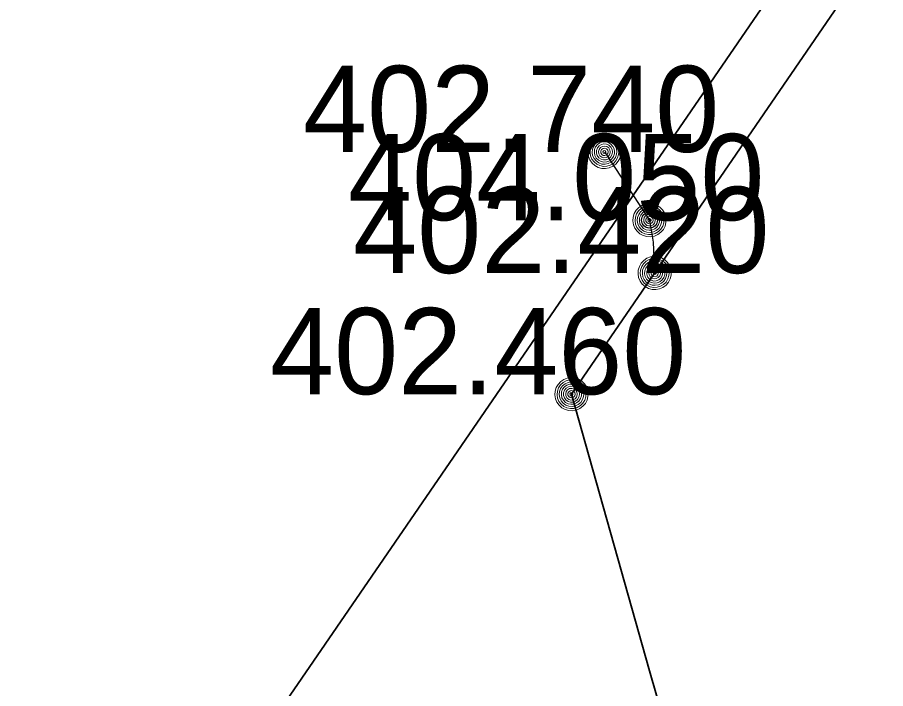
# Model space of a CAD drawing. Extents: x -873619 to -867639, y -1015082 to -1012326.
# Drawn here: x -868007.52 to -867995.42, y -1012730.23 to -1012720.88 of the extents above; entities that cross this region are included whole.
import ezdxf

# ---------------------------------------------------------------- set-up
doc = ezdxf.new("R2010")
doc.units = 0
doc.header["$LTSCALE"] = 0.44
doc.header["$PDMODE"] = 32
doc.header["$PDSIZE"] = 0.22
doc.linetypes.add('DOT_DASHED', pattern=[7.7, 5, -1.2, 0.3, -1.2])
for name, color, linetype, lineweight in [('1', 7, 'Continuous', 13), ('21', 7, 'Continuous', 35), ('23', 7, 'Continuous', 25)]:
    doc.layers.add(name, color=color, linetype=linetype, lineweight=lineweight)
doc.layers.add('33', color=7, linetype='Continuous')

msp = doc.modelspace()

# ---------------------------------------------------------------- linework, layer by layer
at = {"layer": '1'}
for points in [[(-867999.108, -1012722.754), (-867999.115, -1012722.702), (-867999.132, -1012722.652), (-867999.161, -1012722.608), (-867999.198, -1012722.571), (-867999.243, -1012722.544), (-867999.293, -1012722.527), (-867999.346, -1012722.523), (-867999.397, -1012722.53), (-867999.446, -1012722.549), (-867999.49, -1012722.578), (-867999.526, -1012722.617), (-867999.552, -1012722.662), (-867999.568, -1012722.713), (-867999.571, -1012722.765), (-867999.563, -1012722.817), (-867999.543, -1012722.866), (-867999.512, -1012722.909), (-867999.473, -1012722.943), (-867999.427, -1012722.969), (-867999.375, -1012722.983), (-867999.323, -1012722.985), (-867999.272, -1012722.975), (-867999.223, -1012722.954), (-867999.181, -1012722.923), (-867999.147, -1012722.882), (-867999.123, -1012722.836), (-867999.11, -1012722.785)], [(-867999.139, -1012722.754), (-867999.145, -1012722.705), (-867999.162, -1012722.659), (-867999.19, -1012722.619), (-867999.227, -1012722.587), (-867999.271, -1012722.565), (-867999.319, -1012722.554), (-867999.368, -1012722.554), (-867999.414, -1012722.567), (-867999.458, -1012722.591), (-867999.494, -1012722.624), (-867999.521, -1012722.665), (-867999.537, -1012722.712), (-867999.541, -1012722.761), (-867999.534, -1012722.809), (-867999.515, -1012722.854), (-867999.485, -1012722.894), (-867999.446, -1012722.925), (-867999.402, -1012722.945), (-867999.355, -1012722.955), (-867999.306, -1012722.953), (-867999.259, -1012722.938), (-867999.216, -1012722.913), (-867999.181, -1012722.879), (-867999.156, -1012722.837), (-867999.142, -1012722.79)], [(-867999.169, -1012722.754), (-867999.174, -1012722.709), (-867999.191, -1012722.667), (-867999.22, -1012722.632), (-867999.255, -1012722.605), (-867999.298, -1012722.588), (-867999.343, -1012722.583), (-867999.387, -1012722.589), (-867999.429, -1012722.608), (-867999.463, -1012722.636), (-867999.49, -1012722.673), (-867999.507, -1012722.715), (-867999.511, -1012722.76), (-867999.504, -1012722.805), (-867999.485, -1012722.846), (-867999.456, -1012722.88), (-867999.419, -1012722.906), (-867999.375, -1012722.922), (-867999.331, -1012722.925), (-867999.286, -1012722.917), (-867999.245, -1012722.897), (-867999.212, -1012722.868), (-867999.186, -1012722.83), (-867999.172, -1012722.787)], [(-867999.199, -1012722.754), (-867999.203, -1012722.713), (-867999.222, -1012722.676), (-867999.249, -1012722.645), (-867999.284, -1012722.624), (-867999.324, -1012722.613), (-867999.365, -1012722.615), (-867999.404, -1012722.628), (-867999.438, -1012722.652), (-867999.463, -1012722.684), (-867999.478, -1012722.722), (-867999.48, -1012722.763), (-867999.473, -1012722.803), (-867999.453, -1012722.839), (-867999.424, -1012722.868), (-867999.387, -1012722.887), (-867999.347, -1012722.895), (-867999.306, -1012722.891), (-867999.267, -1012722.876), (-867999.235, -1012722.85), (-867999.213, -1012722.816), (-867999.2, -1012722.777)], [(-867999.228, -1012722.754), (-867999.233, -1012722.718), (-867999.252, -1012722.686), (-867999.277, -1012722.661), (-867999.311, -1012722.646), (-867999.348, -1012722.643), (-867999.382, -1012722.651), (-867999.414, -1012722.671), (-867999.436, -1012722.699), (-867999.45, -1012722.733), (-867999.45, -1012722.77), (-867999.439, -1012722.805), (-867999.418, -1012722.834), (-867999.387, -1012722.855), (-867999.353, -1012722.865), (-867999.316, -1012722.863), (-867999.282, -1012722.849), (-867999.255, -1012722.826), (-867999.235, -1012722.794), (-867999.228, -1012722.759)], [(-867999.259, -1012722.754), (-867999.264, -1012722.723), (-867999.281, -1012722.697), (-867999.306, -1012722.68), (-867999.337, -1012722.673), (-867999.368, -1012722.677), (-867999.395, -1012722.694), (-867999.413, -1012722.718), (-867999.421, -1012722.749), (-867999.417, -1012722.779), (-867999.402, -1012722.807), (-867999.377, -1012722.826), (-867999.348, -1012722.835), (-867999.316, -1012722.832), (-867999.289, -1012722.818), (-867999.269, -1012722.794), (-867999.259, -1012722.765)], [(-867999.289, -1012722.754), (-867999.294, -1012722.73), (-867999.311, -1012722.712), (-867999.333, -1012722.703), (-867999.358, -1012722.706), (-867999.379, -1012722.72), (-867999.39, -1012722.742), (-867999.39, -1012722.767), (-867999.377, -1012722.788), (-867999.358, -1012722.802), (-867999.333, -1012722.805), (-867999.309, -1012722.796), (-867999.294, -1012722.778)], [(-867999.319, -1012722.754), (-867999.324, -1012722.739), (-867999.338, -1012722.733), (-867999.353, -1012722.737), (-867999.36, -1012722.751), (-867999.357, -1012722.766), (-867999.343, -1012722.775), (-867999.328, -1012722.772), (-867999.319, -1012722.76)], [(-867998.481, -1012723.704), (-867998.487, -1012723.652), (-867998.504, -1012723.602), (-867998.533, -1012723.558), (-867998.57, -1012723.521), (-867998.615, -1012723.494), (-867998.665, -1012723.477), (-867998.718, -1012723.473), (-867998.77, -1012723.48), (-867998.819, -1012723.499), (-867998.862, -1012723.528), (-867998.898, -1012723.567), (-867998.924, -1012723.612), (-867998.94, -1012723.663), (-867998.943, -1012723.715), (-867998.935, -1012723.767), (-867998.915, -1012723.816), (-867998.884, -1012723.859), (-867998.845, -1012723.893), (-867998.799, -1012723.919), (-867998.748, -1012723.933), (-867998.695, -1012723.935), (-867998.644, -1012723.925), (-867998.596, -1012723.904), (-867998.553, -1012723.873), (-867998.519, -1012723.832), (-867998.495, -1012723.786), (-867998.483, -1012723.735)], [(-867998.511, -1012723.704), (-867998.517, -1012723.655), (-867998.534, -1012723.609), (-867998.562, -1012723.569), (-867998.599, -1012723.537), (-867998.643, -1012723.515), (-867998.691, -1012723.504), (-867998.74, -1012723.504), (-867998.787, -1012723.517), (-867998.83, -1012723.541), (-867998.866, -1012723.574), (-867998.893, -1012723.615), (-867998.909, -1012723.662), (-867998.913, -1012723.711), (-867998.906, -1012723.759), (-867998.887, -1012723.804), (-867998.857, -1012723.844), (-867998.819, -1012723.875), (-867998.775, -1012723.895), (-867998.727, -1012723.905), (-867998.678, -1012723.903), (-867998.631, -1012723.888), (-867998.588, -1012723.863), (-867998.554, -1012723.829), (-867998.528, -1012723.787), (-867998.514, -1012723.74)], [(-867998.541, -1012723.704), (-867998.547, -1012723.659), (-867998.564, -1012723.617), (-867998.592, -1012723.582), (-867998.628, -1012723.555), (-867998.67, -1012723.538), (-867998.715, -1012723.533), (-867998.76, -1012723.539), (-867998.801, -1012723.558), (-867998.836, -1012723.586), (-867998.863, -1012723.623), (-867998.879, -1012723.665), (-867998.883, -1012723.71), (-867998.876, -1012723.755), (-867998.857, -1012723.796), (-867998.828, -1012723.83), (-867998.791, -1012723.856), (-867998.748, -1012723.872), (-867998.703, -1012723.875), (-867998.658, -1012723.867), (-867998.618, -1012723.847), (-867998.584, -1012723.818), (-867998.558, -1012723.78), (-867998.544, -1012723.737)], [(-867998.571, -1012723.704), (-867998.576, -1012723.663), (-867998.594, -1012723.626), (-867998.621, -1012723.595), (-867998.656, -1012723.574), (-867998.696, -1012723.563), (-867998.737, -1012723.565), (-867998.776, -1012723.578), (-867998.81, -1012723.602), (-867998.835, -1012723.634), (-867998.85, -1012723.672), (-867998.853, -1012723.713), (-867998.845, -1012723.753), (-867998.825, -1012723.789), (-867998.796, -1012723.818), (-867998.759, -1012723.837), (-867998.719, -1012723.845), (-867998.678, -1012723.841), (-867998.64, -1012723.826), (-867998.608, -1012723.8), (-867998.585, -1012723.766), (-867998.572, -1012723.727)], [(-867998.601, -1012723.704), (-867998.606, -1012723.668), (-867998.624, -1012723.636), (-867998.65, -1012723.611), (-867998.684, -1012723.596), (-867998.72, -1012723.593), (-867998.755, -1012723.601), (-867998.786, -1012723.621), (-867998.809, -1012723.649), (-867998.822, -1012723.683), (-867998.822, -1012723.72), (-867998.811, -1012723.755), (-867998.79, -1012723.784), (-867998.76, -1012723.805), (-867998.725, -1012723.815), (-867998.688, -1012723.813), (-867998.654, -1012723.799), (-867998.627, -1012723.776), (-867998.608, -1012723.744), (-867998.601, -1012723.709)], [(-867998.631, -1012723.704), (-867998.636, -1012723.673), (-867998.653, -1012723.647), (-867998.679, -1012723.63), (-867998.709, -1012723.623), (-867998.74, -1012723.627), (-867998.767, -1012723.644), (-867998.785, -1012723.668), (-867998.793, -1012723.699), (-867998.789, -1012723.729), (-867998.774, -1012723.757), (-867998.75, -1012723.776), (-867998.72, -1012723.785), (-867998.689, -1012723.782), (-867998.661, -1012723.768), (-867998.641, -1012723.744), (-867998.631, -1012723.715)], [(-867998.661, -1012723.704), (-867998.666, -1012723.68), (-867998.683, -1012723.662), (-867998.706, -1012723.653), (-867998.73, -1012723.656), (-867998.751, -1012723.67), (-867998.762, -1012723.692), (-867998.762, -1012723.717), (-867998.75, -1012723.738), (-867998.73, -1012723.752), (-867998.705, -1012723.755), (-867998.682, -1012723.746), (-867998.666, -1012723.728)], [(-867998.691, -1012723.704), (-867998.696, -1012723.689), (-867998.711, -1012723.683), (-867998.726, -1012723.687), (-867998.733, -1012723.701), (-867998.729, -1012723.716), (-867998.716, -1012723.725), (-867998.701, -1012723.722), (-867998.691, -1012723.71)], [(-867998.409, -1012724.44), (-867998.416, -1012724.388), (-867998.433, -1012724.338), (-867998.462, -1012724.294), (-867998.499, -1012724.257), (-867998.544, -1012724.23), (-867998.593, -1012724.213), (-867998.647, -1012724.209), (-867998.698, -1012724.216), (-867998.747, -1012724.235), (-867998.791, -1012724.264), (-867998.826, -1012724.303), (-867998.853, -1012724.348), (-867998.869, -1012724.399), (-867998.872, -1012724.451), (-867998.864, -1012724.503), (-867998.843, -1012724.552), (-867998.813, -1012724.595), (-867998.774, -1012724.629), (-867998.728, -1012724.655), (-867998.676, -1012724.669), (-867998.624, -1012724.671), (-867998.573, -1012724.661), (-867998.524, -1012724.64), (-867998.482, -1012724.609), (-867998.448, -1012724.568), (-867998.424, -1012724.522), (-867998.411, -1012724.471)], [(-867998.44, -1012724.44), (-867998.446, -1012724.391), (-867998.463, -1012724.345), (-867998.49, -1012724.305), (-867998.527, -1012724.273), (-867998.571, -1012724.251), (-867998.62, -1012724.24), (-867998.669, -1012724.24), (-867998.715, -1012724.253), (-867998.759, -1012724.277), (-867998.794, -1012724.31), (-867998.821, -1012724.351), (-867998.838, -1012724.398), (-867998.842, -1012724.447), (-867998.835, -1012724.495), (-867998.816, -1012724.54), (-867998.786, -1012724.58), (-867998.747, -1012724.611), (-867998.703, -1012724.631), (-867998.656, -1012724.641), (-867998.607, -1012724.639), (-867998.559, -1012724.624), (-867998.517, -1012724.599), (-867998.482, -1012724.565), (-867998.456, -1012724.523), (-867998.443, -1012724.476)], [(-867998.47, -1012724.44), (-867998.475, -1012724.395), (-867998.492, -1012724.353), (-867998.521, -1012724.318), (-867998.556, -1012724.291), (-867998.598, -1012724.274), (-867998.644, -1012724.269), (-867998.688, -1012724.275), (-867998.73, -1012724.294), (-867998.764, -1012724.322), (-867998.791, -1012724.359), (-867998.808, -1012724.401), (-867998.811, -1012724.446), (-867998.804, -1012724.491), (-867998.786, -1012724.532), (-867998.757, -1012724.566), (-867998.72, -1012724.592), (-867998.676, -1012724.608), (-867998.632, -1012724.611), (-867998.587, -1012724.603), (-867998.546, -1012724.583), (-867998.512, -1012724.554), (-867998.487, -1012724.516), (-867998.473, -1012724.473)], [(-867998.5, -1012724.44), (-867998.504, -1012724.399), (-867998.522, -1012724.362), (-867998.549, -1012724.331), (-867998.585, -1012724.31), (-867998.625, -1012724.299), (-867998.666, -1012724.301), (-867998.705, -1012724.314), (-867998.739, -1012724.338), (-867998.764, -1012724.37), (-867998.779, -1012724.408), (-867998.781, -1012724.449), (-867998.774, -1012724.489), (-867998.754, -1012724.525), (-867998.725, -1012724.554), (-867998.688, -1012724.573), (-867998.647, -1012724.581), (-867998.607, -1012724.577), (-867998.568, -1012724.562), (-867998.536, -1012724.536), (-867998.514, -1012724.502), (-867998.5, -1012724.463)], [(-867998.529, -1012724.44), (-867998.534, -1012724.404), (-867998.553, -1012724.372), (-867998.578, -1012724.347), (-867998.612, -1012724.332), (-867998.649, -1012724.329), (-867998.683, -1012724.337), (-867998.715, -1012724.357), (-867998.737, -1012724.385), (-867998.75, -1012724.419), (-867998.75, -1012724.456), (-867998.74, -1012724.491), (-867998.718, -1012724.52), (-867998.688, -1012724.541), (-867998.654, -1012724.551), (-867998.617, -1012724.549), (-867998.583, -1012724.535), (-867998.556, -1012724.512), (-867998.536, -1012724.48), (-867998.529, -1012724.445)], [(-867998.559, -1012724.44), (-867998.565, -1012724.409), (-867998.581, -1012724.383), (-867998.607, -1012724.366), (-867998.637, -1012724.359), (-867998.669, -1012724.363), (-867998.696, -1012724.38), (-867998.713, -1012724.404), (-867998.722, -1012724.435), (-867998.718, -1012724.465), (-867998.703, -1012724.493), (-867998.678, -1012724.512), (-867998.649, -1012724.521), (-867998.617, -1012724.518), (-867998.59, -1012724.504), (-867998.57, -1012724.48), (-867998.559, -1012724.451)], [(-867998.59, -1012724.44), (-867998.595, -1012724.416), (-867998.612, -1012724.398), (-867998.634, -1012724.389), (-867998.659, -1012724.392), (-867998.679, -1012724.406), (-867998.691, -1012724.428), (-867998.691, -1012724.453), (-867998.678, -1012724.474), (-867998.659, -1012724.488), (-867998.634, -1012724.491), (-867998.61, -1012724.482), (-867998.595, -1012724.464)], [(-867998.62, -1012724.44), (-867998.625, -1012724.425), (-867998.639, -1012724.419), (-867998.654, -1012724.423), (-867998.661, -1012724.437), (-867998.657, -1012724.452), (-867998.644, -1012724.461), (-867998.629, -1012724.458), (-867998.62, -1012724.446)], [(-867999.568, -1012726.127), (-867999.574, -1012726.075), (-867999.591, -1012726.025), (-867999.62, -1012725.981), (-867999.657, -1012725.944), (-867999.702, -1012725.917), (-867999.752, -1012725.9), (-867999.805, -1012725.896), (-867999.857, -1012725.903), (-867999.906, -1012725.922), (-867999.949, -1012725.951), (-867999.985, -1012725.99), (-868000.011, -1012726.035), (-868000.027, -1012726.086), (-868000.03, -1012726.138), (-868000.022, -1012726.19), (-868000.002, -1012726.239), (-867999.971, -1012726.282), (-867999.932, -1012726.316), (-867999.886, -1012726.342), (-867999.835, -1012726.356), (-867999.782, -1012726.358), (-867999.731, -1012726.348), (-867999.683, -1012726.327), (-867999.64, -1012726.296), (-867999.606, -1012726.255), (-867999.582, -1012726.209), (-867999.57, -1012726.158)], [(-867999.598, -1012726.127), (-867999.604, -1012726.078), (-867999.621, -1012726.032), (-867999.649, -1012725.992), (-867999.686, -1012725.96), (-867999.73, -1012725.938), (-867999.778, -1012725.927), (-867999.827, -1012725.927), (-867999.874, -1012725.94), (-867999.917, -1012725.964), (-867999.953, -1012725.997), (-867999.98, -1012726.038), (-867999.996, -1012726.085), (-868000, -1012726.134), (-867999.993, -1012726.182), (-867999.974, -1012726.227), (-867999.944, -1012726.267), (-867999.906, -1012726.298), (-867999.862, -1012726.318), (-867999.814, -1012726.328), (-867999.765, -1012726.326), (-867999.718, -1012726.311), (-867999.675, -1012726.286), (-867999.641, -1012726.252), (-867999.615, -1012726.21), (-867999.601, -1012726.163)], [(-867999.628, -1012726.127), (-867999.634, -1012726.082), (-867999.651, -1012726.04), (-867999.679, -1012726.005), (-867999.715, -1012725.978), (-867999.757, -1012725.961), (-867999.802, -1012725.956), (-867999.847, -1012725.962), (-867999.888, -1012725.981), (-867999.923, -1012726.009), (-867999.95, -1012726.046), (-867999.966, -1012726.088), (-867999.97, -1012726.133), (-867999.963, -1012726.178), (-867999.944, -1012726.219), (-867999.915, -1012726.253), (-867999.878, -1012726.279), (-867999.835, -1012726.295), (-867999.79, -1012726.298), (-867999.745, -1012726.29), (-867999.705, -1012726.27), (-867999.671, -1012726.241), (-867999.645, -1012726.203), (-867999.631, -1012726.16)], [(-867999.658, -1012726.127), (-867999.663, -1012726.086), (-867999.681, -1012726.049), (-867999.708, -1012726.018), (-867999.743, -1012725.997), (-867999.783, -1012725.986), (-867999.824, -1012725.988), (-867999.863, -1012726.001), (-867999.897, -1012726.025), (-867999.922, -1012726.057), (-867999.937, -1012726.095), (-867999.94, -1012726.136), (-867999.932, -1012726.176), (-867999.912, -1012726.212), (-867999.883, -1012726.241), (-867999.846, -1012726.26), (-867999.806, -1012726.268), (-867999.765, -1012726.264), (-867999.727, -1012726.249), (-867999.695, -1012726.223), (-867999.672, -1012726.189), (-867999.659, -1012726.15)], [(-867999.688, -1012726.127), (-867999.693, -1012726.091), (-867999.711, -1012726.059), (-867999.737, -1012726.034), (-867999.771, -1012726.019), (-867999.807, -1012726.016), (-867999.842, -1012726.024), (-867999.873, -1012726.044), (-867999.896, -1012726.072), (-867999.909, -1012726.106), (-867999.909, -1012726.143), (-867999.898, -1012726.178), (-867999.877, -1012726.207), (-867999.847, -1012726.228), (-867999.812, -1012726.238), (-867999.775, -1012726.236), (-867999.741, -1012726.222), (-867999.714, -1012726.199), (-867999.695, -1012726.167), (-867999.688, -1012726.132)], [(-867999.718, -1012726.127), (-867999.723, -1012726.096), (-867999.74, -1012726.07), (-867999.766, -1012726.053), (-867999.796, -1012726.046), (-867999.827, -1012726.05), (-867999.854, -1012726.067), (-867999.872, -1012726.091), (-867999.88, -1012726.122), (-867999.876, -1012726.152), (-867999.861, -1012726.18), (-867999.837, -1012726.199), (-867999.807, -1012726.208), (-867999.776, -1012726.205), (-867999.748, -1012726.191), (-867999.728, -1012726.167), (-867999.718, -1012726.138)], [(-867999.748, -1012726.127), (-867999.753, -1012726.103), (-867999.77, -1012726.085), (-867999.793, -1012726.076), (-867999.817, -1012726.079), (-867999.838, -1012726.093), (-867999.849, -1012726.115), (-867999.849, -1012726.14), (-867999.837, -1012726.161), (-867999.817, -1012726.175), (-867999.792, -1012726.178), (-867999.769, -1012726.169), (-867999.753, -1012726.151)], [(-867999.778, -1012726.127), (-867999.783, -1012726.112), (-867999.798, -1012726.106), (-867999.813, -1012726.11), (-867999.82, -1012726.124), (-867999.816, -1012726.139), (-867999.803, -1012726.148), (-867999.788, -1012726.145), (-867999.778, -1012726.133)]]:
    msp.add_lwpolyline(points, close=True, dxfattribs=at)
at = {"layer": '21'}
for points in [[(-868007.52, -1012735.85), (-867995.258, -1012717.991), (-867981.769, -1012701.297)], [(-867994.551, -1012718.479), (-867999.799, -1012726.127), (-867998.71, -1012729.979), (-867996.966, -1012736.043), (-867996.742, -1012736.964), (-867996.7, -1012737.662), (-867996.679, -1012738.122), (-867996.65, -1012739.832), (-867996.798, -1012742.128), (-867996.826, -1012743.328), (-867996.837, -1012743.442), (-867996.68, -1012744.886), (-867996.331, -1012746.924), (-867995.954, -1012748.71), (-867995.326, -1012750.622), (-867994.252, -1012753.385), (-867992.326, -1012757.823), (-867989.674, -1012764.355)]]:
    msp.add_lwpolyline(points, dxfattribs=at)
at = {"layer": '23', "linetype": 'DOT_DASHED'}
msp.add_lwpolyline([(-867999.34, -1012722.754), (-867998.712, -1012723.704), (-867998.663, -1012724.011), (-867998.641, -1012724.44)], dxfattribs=at)
at = {"layer": '33'}
msp.add_point((-867998.712, -1012723.704), dxfattribs=at)

# ---------------------------------------------------------------- texts
at = {"layer": '1'}
for s, p in [('402.740 ', (-868003.54, -1012722.754)), ('404.050 ', (-868002.912, -1012723.704)), ('402.420 ', (-868002.841, -1012724.44)), ('402.460 ', (-868003.999, -1012726.127))]:
    msp.add_text(s, height=1.2, dxfattribs=at).set_placement(p)

doc.saveas('drawing.dxf')
